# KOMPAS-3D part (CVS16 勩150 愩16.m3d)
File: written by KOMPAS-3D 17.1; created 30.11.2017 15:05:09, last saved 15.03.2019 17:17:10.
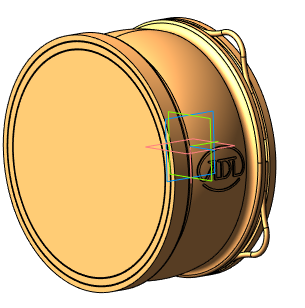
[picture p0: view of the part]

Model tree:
1. Операция без истории:2  (labels: Сталь 20  ГОСТ 1050-2013)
